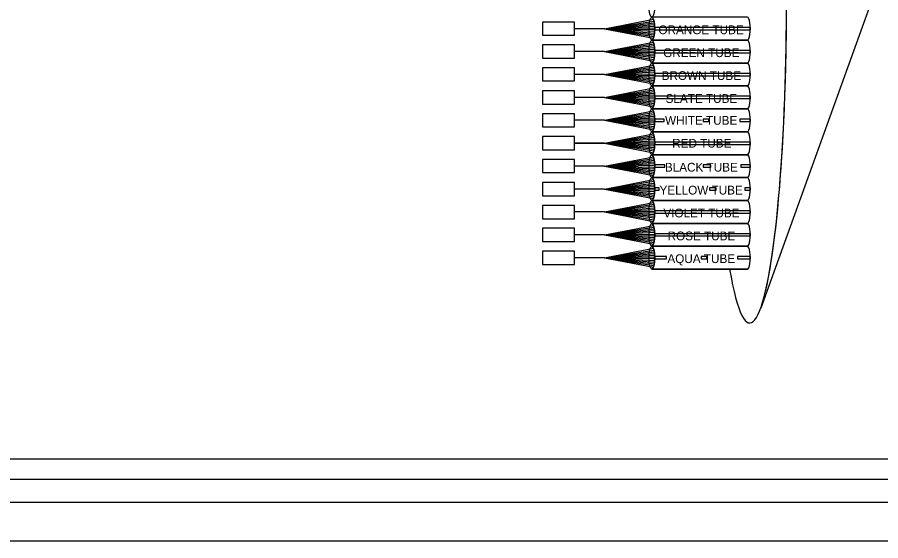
# Model space of a CAD drawing. Extents: x 1805893 to 1833564, y 708898 to 716199.
# Drawn here: x 1833208.6 to 1833434.8, y 714257.9 to 714395 of the extents above; entities that cross this region are included whole.
import ezdxf

# ---------------------------------------------------------------- set-up
doc = ezdxf.new("R2010")
doc.units = 0
for name, color, linetype in [('BR_P_Sub_Hidden', 7, 'Continuous'), ('SH_Border', 7, 'Continuous'), ('SH_Cut_Line', 7, 'Continuous'), ('SH_Data', 7, 'Continuous')]:
    doc.layers.add(name, color=color, linetype=linetype)

msp = doc.modelspace()

# ---------------------------------------------------------------- linework, layer by layer
at = {"layer": 'BR_P_Sub_Hidden'}
for points in [[(1833067.2, 714538.6), (1833508.62, 714538.6), (1833508.62, 714273.91), (1833067.2, 714273.91)], [(1833135.95, 714528.32), (1833459.05, 714528.32), (1833459.05, 714279.3), (1833135.95, 714279.3)]]:
    msp.add_lwpolyline(points, close=True, dxfattribs=at)
at = {"layer": 'SH_Border'}
msp.add_lwpolyline([(1832923.78, 714687.91), (1833553.78, 714687.91), (1833553.78, 714267.91), (1832923.78, 714267.91)], close=True, dxfattribs=at)
at = {"layer": 'SH_Cut_Line'}
msp.add_lwpolyline([(1832883.78, 714257.91), (1833563.78, 714257.91), (1833563.78, 714697.91), (1832883.78, 714697.91)], close=True, dxfattribs=at)
at = {"layer": 'SH_Data'}
for p, q in [((1833362.41, 714392.04), (1833375.25, 714394.51)), ((1833362.41, 714392.04), (1833375.38, 714394.06)), ((1833362.41, 714392.04), (1833375.46, 714393.61)), ((1833362.41, 714392.04), (1833375.52, 714393.16)), ((1833399.88, 714395.04), (1833374.83, 714395.04)), ((1833362.41, 714392.04), (1833354.58, 714392.04)), ((1833362.41, 714392.04), (1833354.58, 714392.04)), ((1833362.41, 714392.04), (1833375.56, 714392.71)), ((1833362.41, 714392.04), (1833375.57, 714392.26)), ((1833362.41, 714392.04), (1833375.52, 714390.91)), ((1833362.41, 714392.04), (1833375.46, 714390.46)), ((1833362.41, 714392.04), (1833375.38, 714390.01)), ((1833362.41, 714392.04), (1833375.25, 714389.56)), ((1833362.41, 714392.04), (1833375.56, 714391.36)), ((1833362.41, 714392.04), (1833375.57, 714391.81)), ((1833399.88, 714389.04), (1833374.83, 714389.04)), ((1833374.83, 714389.04), (1833399.88, 714389.04)), ((1833362.41, 714386.04), (1833375.25, 714388.51)), ((1833362.41, 714386.04), (1833375.38, 714388.06)), ((1833362.41, 714386.04), (1833375.46, 714387.61)), ((1833362.41, 714386.04), (1833375.52, 714387.16)), ((1833362.41, 714386.04), (1833375.56, 714386.71)), ((1833362.41, 714386.04), (1833354.58, 714386.04)), ((1833362.41, 714386.04), (1833354.58, 714386.04)), ((1833362.41, 714386.04), (1833375.57, 714386.26)), ((1833362.41, 714386.04), (1833375.52, 714384.91)), ((1833362.41, 714386.04), (1833375.46, 714384.46)), ((1833362.41, 714386.04), (1833375.38, 714384.01)), ((1833362.41, 714386.04), (1833375.25, 714383.56)), ((1833362.41, 714386.04), (1833375.56, 714385.36)), ((1833362.41, 714386.04), (1833375.57, 714385.81)), ((1833362.41, 714380.04), (1833375.25, 714382.51)), ((1833362.41, 714380.04), (1833375.38, 714382.06)), ((1833374.83, 714383.04), (1833399.88, 714383.04)), ((1833399.88, 714383.04), (1833374.83, 714383.04)), ((1833362.41, 714380.04), (1833354.58, 714380.04)), ((1833362.41, 714380.04), (1833354.58, 714380.04)), ((1833362.41, 714380.04), (1833375.46, 714381.61)), ((1833362.41, 714380.04), (1833375.52, 714381.16)), ((1833362.41, 714380.04), (1833375.56, 714380.71)), ((1833362.41, 714380.04), (1833375.57, 714380.26)), ((1833362.41, 714380.04), (1833375.52, 714378.91)), ((1833362.41, 714380.04), (1833375.46, 714378.46)), ((1833362.41, 714380.04), (1833375.38, 714378.01)), ((1833362.41, 714380.04), (1833375.25, 714377.56)), ((1833362.41, 714380.04), (1833375.56, 714379.36)), ((1833362.41, 714380.04), (1833375.57, 714379.81)), ((1833362.41, 714374.04), (1833375.25, 714376.51)), ((1833362.41, 714374.04), (1833375.38, 714376.06)), ((1833362.41, 714374.04), (1833375.46, 714375.61)), ((1833362.41, 714374.04), (1833375.52, 714375.16)), ((1833374.83, 714377.04), (1833399.88, 714377.04)), ((1833399.88, 714377.04), (1833374.83, 714377.04)), ((1833362.41, 714374.04), (1833354.58, 714374.04)), ((1833362.41, 714374.04), (1833354.58, 714374.04)), ((1833362.41, 714374.04), (1833375.56, 714374.71)), ((1833362.41, 714374.04), (1833375.57, 714374.26)), ((1833362.41, 714374.04), (1833375.52, 714372.91)), ((1833362.41, 714374.04), (1833375.46, 714372.46)), ((1833362.41, 714374.04), (1833375.38, 714372.01)), ((1833362.41, 714374.04), (1833375.25, 714371.56)), ((1833362.41, 714374.04), (1833375.56, 714373.36)), ((1833362.41, 714374.04), (1833375.57, 714373.81)), ((1833374.83, 714371.04), (1833399.88, 714371.04)), ((1833399.88, 714371.04), (1833374.83, 714371.04)), ((1833362.41, 714368.04), (1833375.25, 714370.51)), ((1833362.41, 714368.04), (1833375.38, 714370.06)), ((1833362.41, 714368.04), (1833375.46, 714369.61)), ((1833362.41, 714368.04), (1833375.52, 714369.16)), ((1833362.41, 714368.04), (1833375.56, 714368.71)), ((1833362.41, 714368.04), (1833354.58, 714368.04)), ((1833362.41, 714368.04), (1833354.58, 714368.04)), ((1833362.41, 714368.04), (1833375.57, 714368.26)), ((1833362.41, 714368.04), (1833375.52, 714366.91)), ((1833362.41, 714368.04), (1833375.46, 714366.46)), ((1833362.41, 714368.04), (1833375.38, 714366.01)), ((1833362.41, 714368.04), (1833375.25, 714365.56)), ((1833362.41, 714368.04), (1833375.56, 714367.36)), ((1833362.41, 714368.04), (1833375.57, 714367.81)), ((1833362.41, 714362.04), (1833375.25, 714364.51)), ((1833362.41, 714362.04), (1833375.38, 714364.06)), ((1833374.83, 714365.04), (1833399.88, 714365.04)), ((1833399.88, 714365.04), (1833374.83, 714365.04)), ((1833354.58, 714362.04), (1833362.41, 714362.04)), ((1833362.41, 714362.04), (1833354.58, 714362.04)), ((1833362.41, 714362.04), (1833375.46, 714363.61)), ((1833362.41, 714362.04), (1833375.52, 714363.16)), ((1833362.41, 714362.04), (1833375.56, 714362.71)), ((1833362.41, 714362.04), (1833375.57, 714362.26)), ((1833362.41, 714362.04), (1833375.52, 714360.91)), ((1833362.41, 714362.04), (1833375.46, 714360.46)), ((1833362.41, 714362.04), (1833375.38, 714360.01)), ((1833362.41, 714362.04), (1833375.25, 714359.56)), ((1833362.41, 714362.04), (1833375.56, 714361.36)), ((1833362.41, 714362.04), (1833375.57, 714361.81)), ((1833362.41, 714356.04), (1833375.25, 714358.51)), ((1833362.41, 714356.04), (1833375.38, 714358.06)), ((1833362.41, 714356.04), (1833375.46, 714357.61)), ((1833362.41, 714356.04), (1833375.52, 714357.16)), ((1833374.83, 714359.04), (1833399.88, 714359.04)), ((1833399.88, 714359.04), (1833374.83, 714359.04)), ((1833362.41, 714356.04), (1833354.58, 714356.04)), ((1833362.41, 714356.04), (1833354.58, 714356.04)), ((1833362.41, 714356.04), (1833375.56, 714356.71)), ((1833362.41, 714356.04), (1833375.57, 714356.26)), ((1833362.41, 714356.04), (1833375.52, 714354.91)), ((1833362.41, 714356.04), (1833375.46, 714354.46)), ((1833362.41, 714356.04), (1833375.38, 714354.01)), ((1833362.41, 714356.04), (1833375.25, 714353.56)), ((1833362.41, 714356.04), (1833375.56, 714355.36)), ((1833362.41, 714356.04), (1833375.57, 714355.81)), ((1833362.41, 714350.04), (1833375.25, 714352.51)), ((1833399.88, 714353.04), (1833374.83, 714353.04)), ((1833374.83, 714353.04), (1833399.88, 714353.04)), ((1833362.41, 714350.04), (1833375.38, 714352.06)), ((1833362.41, 714350.04), (1833375.46, 714351.61)), ((1833362.41, 714350.04), (1833375.52, 714351.16)), ((1833362.41, 714350.04), (1833375.56, 714350.71)), ((1833362.41, 714350.04), (1833375.57, 714350.26)), ((1833362.41, 714350.04), (1833354.58, 714350.04)), ((1833362.41, 714350.04), (1833354.58, 714350.04)), ((1833362.41, 714350.04), (1833375.52, 714348.91)), ((1833362.41, 714350.04), (1833375.46, 714348.46)), ((1833362.41, 714350.04), (1833375.38, 714348.01)), ((1833362.41, 714350.04), (1833375.25, 714347.56)), ((1833362.41, 714350.04), (1833375.56, 714349.36)), ((1833362.41, 714350.04), (1833375.57, 714349.81)), ((1833362.41, 714344.04), (1833375.25, 714346.51)), ((1833362.41, 714344.04), (1833375.38, 714346.06)), ((1833374.83, 714347.04), (1833399.88, 714347.04)), ((1833399.88, 714347.04), (1833374.83, 714347.04)), ((1833362.41, 714344.04), (1833354.58, 714344.04)), ((1833362.41, 714344.04), (1833354.58, 714344.04)), ((1833362.41, 714344.04), (1833375.46, 714345.61)), ((1833362.41, 714344.04), (1833375.52, 714345.16)), ((1833362.41, 714344.04), (1833375.56, 714344.71)), ((1833362.41, 714344.04), (1833375.57, 714344.26)), ((1833362.41, 714344.04), (1833375.52, 714342.91)), ((1833362.41, 714344.04), (1833375.46, 714342.46)), ((1833362.41, 714344.04), (1833375.38, 714342.01)), ((1833362.41, 714344.04), (1833375.25, 714341.56)), ((1833362.41, 714344.04), (1833375.56, 714343.36)), ((1833362.41, 714344.04), (1833375.57, 714343.81)), ((1833362.41, 714338.04), (1833375.25, 714340.51)), ((1833362.41, 714338.04), (1833375.38, 714340.06)), ((1833362.41, 714338.04), (1833375.46, 714339.61)), ((1833362.41, 714338.04), (1833375.52, 714339.16)), ((1833374.83, 714341.04), (1833399.88, 714341.04)), ((1833399.88, 714341.04), (1833374.83, 714341.04)), ((1833362.41, 714338.04), (1833354.58, 714338.04)), ((1833362.41, 714338.04), (1833354.58, 714338.04)), ((1833362.41, 714338.04), (1833375.56, 714338.71)), ((1833362.41, 714338.04), (1833375.57, 714338.26)), ((1833362.41, 714338.04), (1833375.52, 714336.91)), ((1833362.41, 714338.04), (1833375.46, 714336.46)), ((1833362.41, 714338.04), (1833375.38, 714336.01)), ((1833362.41, 714338.04), (1833375.25, 714335.56)), ((1833362.41, 714338.04), (1833375.56, 714337.36)), ((1833362.41, 714338.04), (1833375.57, 714337.81)), ((1833362.41, 714332.04), (1833375.25, 714334.51)), ((1833374.83, 714335.04), (1833399.88, 714335.04)), ((1833399.88, 714335.04), (1833374.83, 714335.04)), ((1833362.41, 714332.04), (1833375.38, 714334.06)), ((1833362.41, 714332.04), (1833375.46, 714333.61)), ((1833362.41, 714332.04), (1833375.52, 714333.16)), ((1833362.41, 714332.04), (1833375.56, 714332.71)), ((1833362.41, 714332.04), (1833375.57, 714332.26)), ((1833362.41, 714332.04), (1833354.58, 714332.04)), ((1833362.41, 714332.01), (1833354.58, 714332)), ((1833362.41, 714332.04), (1833375.52, 714330.91)), ((1833362.41, 714332.04), (1833375.46, 714330.46)), ((1833362.41, 714332.04), (1833375.38, 714330.01)), ((1833362.41, 714332.04), (1833375.25, 714329.56)), ((1833362.41, 714332.04), (1833375.56, 714331.36)), ((1833362.41, 714332.04), (1833375.57, 714331.81)), ((1833374.83, 714329.04), (1833399.88, 714329.04)), ((1833399.88, 714329.04), (1833374.83, 714329.04)), ((1833374.83, 714329.04), (1833395.19, 714329.04))]:
    msp.add_line(p, q, dxfattribs=at)
msp.add_lwpolyline([(1833403.35, 714483.23), (1833432.95, 714401.04), (1833403.35, 714318.84)], dxfattribs=at)
msp.add_lwpolyline([(1833403.35, 714483.23), (1833432.95, 714401.04), (1833403.35, 714318.84)], dxfattribs=at)
for points in [[(1833354.58, 714390.31), (1833354.58, 714393.77), (1833346.13, 714393.77), (1833346.13, 714390.31)], [(1833400.62, 714392.34), (1833375.57, 714392.34), (1833375.57, 714391.74), (1833400.62, 714391.74)], [(1833354.58, 714384.34), (1833354.58, 714387.8), (1833346.13, 714387.8), (1833346.13, 714384.34)], [(1833400.62, 714386.34), (1833375.57, 714386.34), (1833375.57, 714385.74), (1833400.62, 714385.74)], [(1833354.58, 714378.35), (1833354.58, 714381.81), (1833346.13, 714381.81), (1833346.13, 714378.35)], [(1833400.62, 714380.34), (1833375.57, 714380.34), (1833375.57, 714379.74), (1833400.62, 714379.74)], [(1833354.58, 714372.31), (1833354.58, 714375.77), (1833346.13, 714375.77), (1833346.13, 714372.31)], [(1833400.62, 714374.34), (1833375.57, 714374.34), (1833375.57, 714373.74), (1833400.62, 714373.74)], [(1833354.58, 714366.31), (1833354.58, 714369.77), (1833346.13, 714369.77), (1833346.13, 714366.31)], [(1833378.06, 714368.34), (1833375.57, 714368.34), (1833375.57, 714367.74), (1833378.06, 714367.74)], [(1833389.79, 714368.34), (1833388.31, 714368.34), (1833388.31, 714367.74), (1833389.79, 714367.74)], [(1833400.62, 714368.34), (1833397.9, 714368.34), (1833397.9, 714367.74), (1833400.62, 714367.74)], [(1833354.58, 714360.34), (1833354.58, 714363.8), (1833346.13, 714363.8), (1833346.13, 714360.34)], [(1833400.62, 714362.34), (1833375.57, 714362.34), (1833375.57, 714361.74), (1833400.62, 714361.74)], [(1833354.58, 714354.35), (1833354.58, 714357.81), (1833346.13, 714357.81), (1833346.13, 714354.35)], [(1833378.18, 714356.34), (1833375.57, 714356.34), (1833375.57, 714355.74), (1833378.18, 714355.74)], [(1833390.25, 714356.34), (1833388.27, 714356.34), (1833388.27, 714355.74), (1833390.25, 714355.74)], [(1833400.62, 714356.34), (1833398.15, 714356.34), (1833398.15, 714355.74), (1833400.62, 714355.74)], [(1833354.58, 714348.27), (1833354.58, 714351.73), (1833346.13, 714351.73), (1833346.13, 714348.27)], [(1833376.7, 714350.34), (1833375.57, 714350.34), (1833375.57, 714349.74), (1833376.7, 714349.74)], [(1833391.66, 714350.34), (1833389.94, 714350.34), (1833389.94, 714349.74), (1833391.66, 714349.74)], [(1833400.62, 714350.34), (1833399.16, 714350.34), (1833399.16, 714349.74), (1833400.62, 714349.74)], [(1833354.58, 714342.27), (1833354.58, 714345.73), (1833346.13, 714345.73), (1833346.13, 714342.27)], [(1833400.62, 714344.34), (1833375.57, 714344.34), (1833375.57, 714343.74), (1833400.62, 714343.74)], [(1833354.58, 714336.31), (1833354.58, 714339.77), (1833346.13, 714339.77), (1833346.13, 714336.31)], [(1833400.62, 714338.34), (1833375.57, 714338.34), (1833375.57, 714337.74), (1833400.62, 714337.74)], [(1833354.58, 714330.31), (1833354.58, 714333.77), (1833346.13, 714333.77), (1833346.13, 714330.31)], [(1833378.68, 714332.34), (1833375.57, 714332.34), (1833375.57, 714331.74), (1833378.68, 714331.74)], [(1833389.26, 714332.34), (1833387.74, 714332.34), (1833387.74, 714331.74), (1833389.26, 714331.74)], [(1833400.62, 714332.34), (1833397.26, 714332.34), (1833397.26, 714331.74), (1833400.62, 714331.74)]]:
    msp.add_lwpolyline(points, close=True, dxfattribs=at)
for centre, major_axis, ratio, start_param, end_param in [((1833400.48, 714401.04), (0, -86.09), 0.112175, 5.702888, 10.005075), ((1833400.48, 714401.04), (0, -86.09), 0.112175, 5.702888, 10.005075), ((1833400.48, 714401.04), (0, -86.09), 0.112175, 0.302036, 2.839557), ((1833374.83, 714392.04), (0, -3), 0.25, 0, 3.141593), ((1833399.88, 714392.04), (0, -3), 0.25, 0, 3.141593), ((1833399.88, 714392.04), (0, -3), 0.25, 0, 3.141593), ((1833374.83, 714386.04), (0, -3), 0.25, 0, 3.141593), ((1833399.88, 714386.04), (0, -3), 0.25, 0, 3.141593), ((1833399.88, 714386.04), (0, -3), 0.25, 0, 3.141593), ((1833374.83, 714380.04), (0, -3), 0.25, 0, 3.141593), ((1833399.88, 714380.04), (0, -3), 0.25, 0, 3.141593), ((1833399.88, 714380.04), (0, -3), 0.25, 0, 3.141593), ((1833374.83, 714374.04), (0, -3), 0.25, 0, 3.141593), ((1833399.88, 714374.04), (0, -3), 0.25, 0, 3.141593), ((1833399.88, 714374.04), (0, -3), 0.25, 0, 3.141593), ((1833374.83, 714368.04), (0, -3), 0.25, 0, 3.141593), ((1833399.88, 714368.04), (0, -3), 0.25, 0, 3.141593), ((1833399.88, 714368.04), (0, -3), 0.25, 0, 3.141593), ((1833374.83, 714362.04), (0, -3), 0.25, 0, 3.141593), ((1833399.88, 714362.04), (0, -3), 0.25, 0, 3.141593), ((1833399.88, 714362.04), (0, -3), 0.25, 0, 3.141593), ((1833374.83, 714356.04), (0, -3), 0.25, 0, 3.141593), ((1833399.88, 714356.04), (0, -3), 0.25, 0, 3.141593), ((1833399.88, 714356.04), (0, -3), 0.25, 0, 3.141593), ((1833374.83, 714350.04), (0, -3), 0.25, 0, 3.141593), ((1833399.88, 714350.04), (0, -3), 0.25, 0, 3.141593), ((1833399.88, 714350.04), (0, -3), 0.25, 0, 3.141593), ((1833374.83, 714344.04), (0, -3), 0.25, 0, 3.141593), ((1833399.88, 714344.04), (0, -3), 0.25, 0, 3.141593), ((1833399.88, 714344.04), (0, -3), 0.25, 0, 3.141593), ((1833374.83, 714338.04), (0, -3), 0.25, 0, 3.141593), ((1833399.88, 714338.04), (0, -3), 0.25, 0, 3.141593), ((1833399.88, 714338.04), (0, -3), 0.25, 0, 3.141593), ((1833374.83, 714332.04), (0, -3), 0.25, 0, 3.141593), ((1833399.88, 714332.04), (0, -3), 0.25, 0, 3.141593), ((1833399.88, 714332.04), (0, -3), 0.25, 0, 3.141593)]:
    msp.add_ellipse(centre, major_axis=major_axis, ratio=ratio, start_param=start_param, end_param=end_param, dxfattribs=at)
for centre in [(1833374.83, 714398.04), (1833374.83, 714392.04), (1833374.83, 714386.04), (1833374.83, 714380.04), (1833374.83, 714374.04), (1833374.83, 714368.04), (1833374.83, 714362.04), (1833374.83, 714356.04), (1833374.83, 714350.04), (1833374.83, 714344.04), (1833374.83, 714338.04), (1833374.83, 714332.04)]:
    msp.add_ellipse(centre, major_axis=(0, -3), ratio=0.25, dxfattribs=at)

# ---------------------------------------------------------------- texts
for s, height, p in [('ORANGE TUBE', 2.2947, (1833376.55, 714390.61)), ('GREEN TUBE', 2.295, (1833377.81, 714384.61)), ('BROWN TUBE', 2.295, (1833377.39, 714378.61)), ('SLATE TUBE', 2.295, (1833378.42, 714372.61)), ('WHITE TUBE', 2.295, (1833378.28, 714366.89)), ('RED TUBE', 2.295, (1833380.15, 714360.89)), ('BLACK TUBE', 2.295, (1833378.24, 714354.61)), ('YELLOW TUBE', 2.2947, (1833376.83, 714348.61)), ('VIOLET TUBE', 2.2947, (1833377.84, 714342.61)), ('ROSE TUBE', 2.295, (1833378.95, 714336.61)), ('AQUA TUBE', 2.295, (1833378.9, 714330.65))]:
    msp.add_text(s, height=height, rotation=360, dxfattribs=at).set_placement(p)

doc.saveas('drawing.dxf')
